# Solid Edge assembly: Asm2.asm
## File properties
Author: f_grande
Template: Weldment.asm
Last saved by: f_grande
Revision: 8
Application: Solid Edge
Tipo di contenuto documento: 100
Weld Bead Density: 0,000 kg/m^3
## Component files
SUPP 3 ASSE Z.par
SUPP_CHIOCC_Z.psm
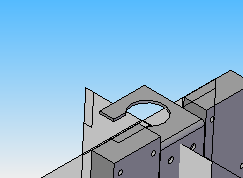
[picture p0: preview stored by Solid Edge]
